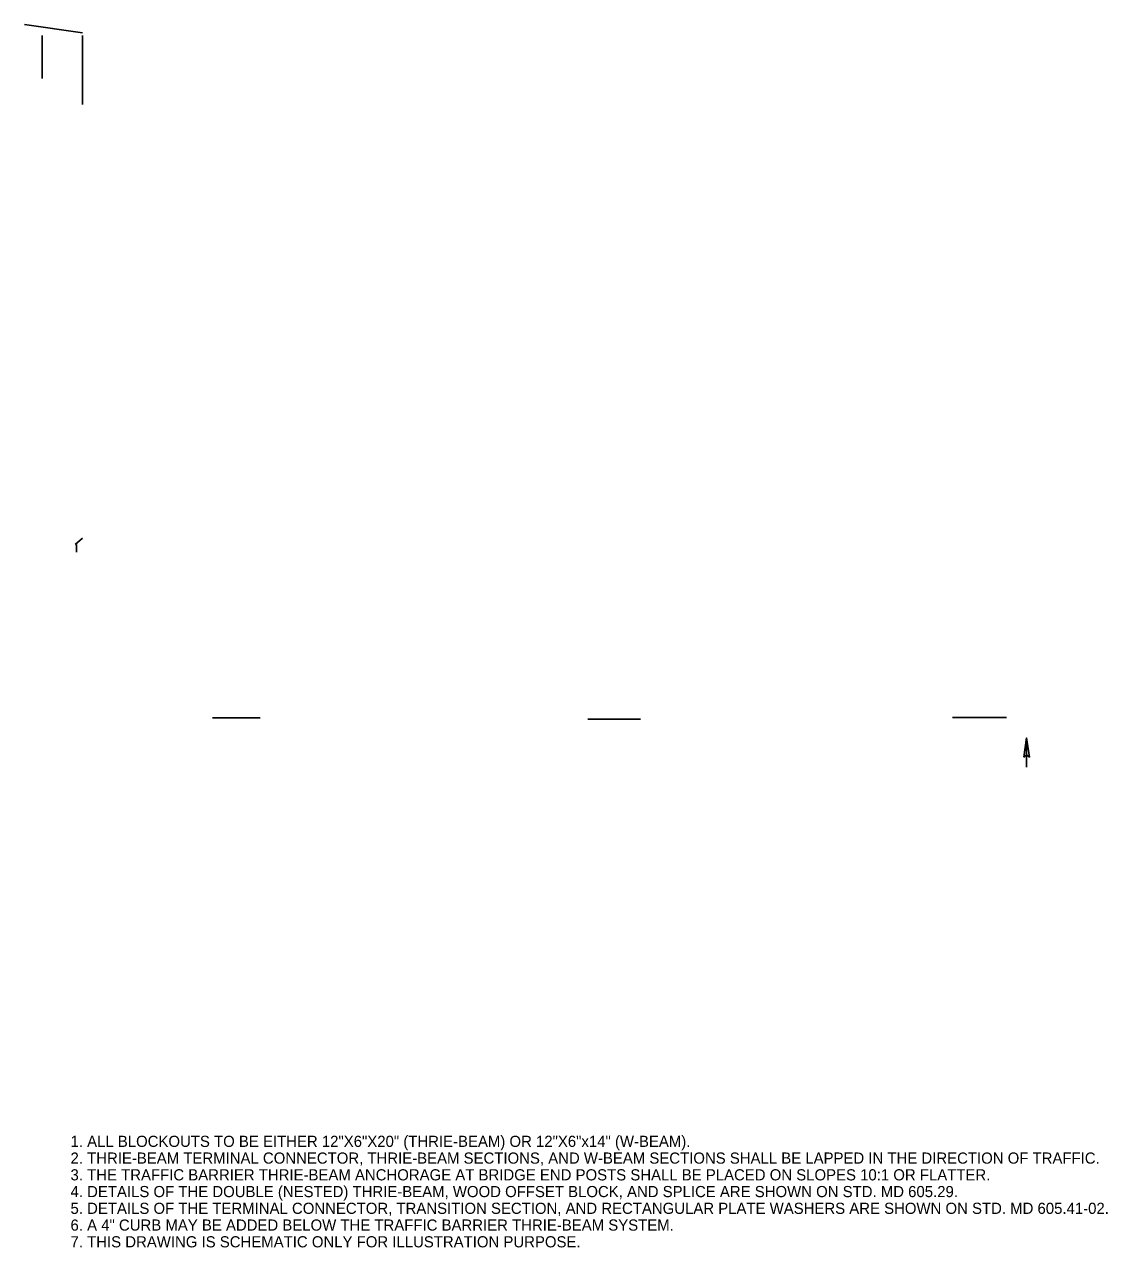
# Model space of a CAD drawing. Extents: x 12.2 to 54.5, y -7.8 to 16.1.
# Drawn here: x 36.29 to 42.11, y -0.5 to 6.07 of the extents above; entities that cross this region are included whole.
import ezdxf

# ---------------------------------------------------------------- set-up
doc = ezdxf.new("R2010")
doc.units = 0
for name, color, linetype in [('DETL-DIMS', 7, 'Continuous'), ('DETL-LINE', 7, 'Continuous'), ('DETL-NOTE', 7, 'Continuous')]:
    doc.layers.add(name, color=color, linetype=linetype)

msp = doc.modelspace()

# ---------------------------------------------------------------- linework, layer by layer
at = {"layer": 'DETL-DIMS'}
for p, q in [((37.2976, 2.3426), (37.5541, 2.3426)), ((39.3146, 2.336), (39.5981, 2.336)), ((41.2747, 2.3448), (41.5655, 2.3448)), ((41.6584, 2.1313), (41.6729, 2.2347)), ((41.6729, 2.2347), (41.6729, 2.0775)), ((41.6886, 2.1315), (41.6729, 2.2347)), ((41.6584, 2.1313), (41.6734, 2.1443)), ((41.6886, 2.1315), (41.6734, 2.1443))]:
    msp.add_line(p, q, dxfattribs=at)
msp.add_lwpolyline([(41.6584, 2.1313), (41.6729, 2.2347), (41.6886, 2.1315), (41.6734, 2.1443)], close=True, dxfattribs=at)
at = {"layer": 'DETL-LINE'}
for p, q in [((36.599, 6.0256), (36.2866, 6.0697)), ((36.3815, 6.0096), (36.3815, 5.7796)), ((36.5989, 6.0096), (36.5989, 5.7796)), ((36.5989, 5.7796), (36.5989, 5.6393)), ((36.5989, 5.7796), (36.5989, 5.6393)), ((36.5593, 3.274), (36.5991, 3.3075)), ((36.5657, 3.2329), (36.5657, 3.2741))]:
    msp.add_line(p, q, dxfattribs=at)

# ---------------------------------------------------------------- texts
at = {"layer": 'DETL-NOTE'}
for s, p in [('1. ALL BLOCKOUTS TO BE EITHER 12"X6"X20" (THRIE-BEAM) OR 12"X6"x14" (W-BEAM).', (36.5342, 0.036)), ('2. THRIE-BEAM TERMINAL CONNECTOR, THRIE-BEAM SECTIONS, AND W-BEAM SECTIONS SHALL BE LAPPED IN THE DIRECTION OF TRAFFIC.', (36.5342, -0.054)), ('3. THE TRAFFIC BARRIER THRIE-BEAM ANCHORAGE AT BRIDGE END POSTS SHALL BE PLACED ON SLOPES 10:1 OR FLATTER.', (36.5342, -0.144)), ('4. DETAILS OF THE DOUBLE (NESTED) THRIE-BEAM, WOOD OFFSET BLOCK, AND SPLICE ARE SHOWN ON STD. MD 605.29.', (36.5342, -0.234)), ('5. DETAILS OF THE TERMINAL CONNECTOR, TRANSITION SECTION, AND RECTANGULAR PLATE WASHERS ARE SHOWN ON STD. MD 605.41-02.', (36.5342, -0.324)), ('6. A 4" CURB MAY BE ADDED BELOW THE TRAFFIC BARRIER THRIE-BEAM SYSTEM.', (36.5342, -0.414)), ('7. THIS DRAWING IS SCHEMATIC ONLY FOR ILLUSTRATION PURPOSE.', (36.5342, -0.504))]:
    msp.add_text(s, height=0.06, rotation=360, dxfattribs=at).set_placement(p)

doc.saveas('drawing.dxf')
